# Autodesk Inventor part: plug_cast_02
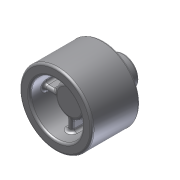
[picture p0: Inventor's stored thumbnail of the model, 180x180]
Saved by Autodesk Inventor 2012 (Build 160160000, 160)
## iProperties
Created: 2002-07
Part Number: plug_cast_02
Document SubType Name: Modeling
Designer: Lieven Grauls
Stock Number: plug_cast_02
Project: Valve Techcamp 2008
Density: 1 g/cm^3
Material: Default
Company: Autodesk
Control State: 0
Master: False
Checked Out: False
Shininess: 64.0
Length Units: 11269
Angle Units: 11279
Time Units: 11290
Mass Units: 11283
Length Display Precision: 3
Angle Display Precision: 2
Density: 0.0
Volumn: 0.0
Area: 0.0
PropertySet Name: Model Information
Author: Lieven Grauls
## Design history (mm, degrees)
sketch "Sketch1"
  geometry: L1 (19, 0)-(26.5, 0); L2 (26.5, 0)-(26.5, 35); L3 (26.5, 35)-(19, 35); L4 (19, 35)-(19, 0); L5 (0, -10)-(0, 60) reference; L6 (0, 50)-(11, 50); L7 (11, 50)-(11, 10); L8 (11, 10)-(0, 10); 1 further point
  constraints: 14 end point, 3 parallel, 3 perpendicular, 2 point on line, 1 horizontal alignment
  dimensions: "d0" = 22 diameter of L6.end L5; "d1" = 38 diameter of L4 L5; "d2" = 53 diameter of L2.end L5; "d3" = 10 distance between parallel lines of L1 L8; "d4" = 35 distance between parallel lines of L3 L1; "d5" = 50 distance between parallel lines of L6 L1
revolve "Revolution1" stored, may be unused: angle "d6" = 90 deg
revolve "Revolution2" stored, may be unused: angle "d7" = 90 deg
fillet "Fillet10" dims "d21" = 2
fillet "Fillet12" dims "d23" = 1
sketch "Sketch2"
  geometry: L1 (-3, 22.607)-(-3, 4.734); L2 (3, 22.607)-(3, 4.734); L3 (0, 37.1)-(0, -37.1) reference; L4 (-3, 22.607)-(3, 22.607); L5 (3, 4.734)-(-3, 4.734)
  constraints: 8 end point, 2 parallel, 1 perpendicular, 1 vertical
  dimensions: "d8" = 6 distance between parallel lines of L2 L1; "d9" = 3 distance between parallel lines of L1 L3 (= 0.5 x d8)
extrude "Extrusion1" join sketch "Sketch2" stored distance "d10" = 10; taper "d11" = -3 deg
fillet "Fillet13" dims "d24" = 2.5
fillet "Fillet8"
fillet "Fillet14" dims "d25" = 2
pattern_circular "Circular Pattern1" dims "d14" = 360 deg
fillet "Fillet1" dims "d15" = 1.5
node "Volumenkörper1"
node "Volumenkörpern"
node "Oberflächenkörpern"
